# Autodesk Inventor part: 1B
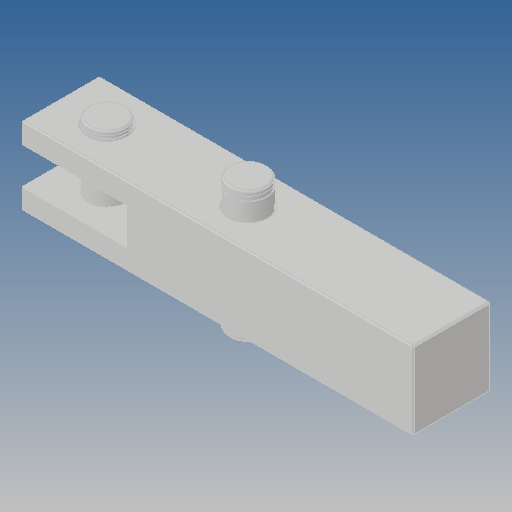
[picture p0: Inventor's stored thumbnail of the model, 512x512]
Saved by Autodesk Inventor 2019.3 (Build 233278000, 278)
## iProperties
Created: 2013-07
Part Number: 1B
Material: Ogólny
Document SubType Name: Modeling
Designer: Admin
Density: 1 g/cm^3
Appearance: Domyślna
Author: Admin
Revision Number: ÈÎºÎ
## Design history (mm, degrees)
feature "CHLC-50-02-1-solid1"
feature "CALC-100-03-2-solid1"
feature "CALC-100-01-1-solid1"
node "Bryła1"
node "Bryła4"
node "Bryła6"
node "Bryła7"
